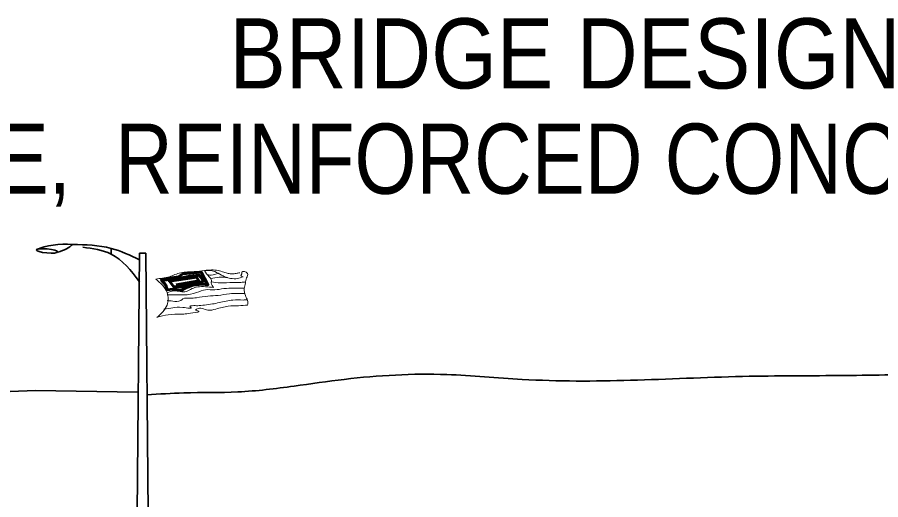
# Model space of a CAD drawing. Extents: x 763.8 to 797.8, y -170.3 to -127.3.
# Drawn here: x 775.84 to 783.6, y -141.62 to -137.29 of the extents above; entities that cross this region are included whole.
import ezdxf
from ezdxf.enums import TextEntityAlignment as Align

# ---------------------------------------------------------------- set-up
doc = ezdxf.new("R2010")
doc.units = 0
doc.header["$LTSCALE"] = 0.077
doc.layers.add('1', color=7, linetype='Continuous', lineweight=35)
doc.layers.add('63', color=7, linetype='Continuous', lineweight=13)

msp = doc.modelspace()

# ---------------------------------------------------------------- linework, layer by layer
at = {"layer": '63', "lineweight": 35}
for p, q in [((776.68675, -139.41675), (776.68675, -139.36583)), ((776.9215, -141.7415), (776.94183, -139.40917)), ((776.94183, -139.40917), (776.99792, -139.40917)), ((777.01825, -141.7415), (776.99792, -139.40917))]:
    msp.add_line(p, q, dxfattribs=at)
at = {"layer": '63', "lineweight": 60}
msp.add_lwpolyline([(777.13792, -139.64592), (777.29075, -139.6205), (777.33142, -139.595), (777.49442, -139.57975), (777.5555, -139.69175), (777.50458, -139.68667), (777.42317, -139.69683), (777.35183, -139.72233), (777.31108, -139.74267), (777.23975, -139.7325), (777.18883, -139.73758), (777.17867, -139.69683), (777.13792, -139.651), (777.23975, -139.64592), (777.39258, -139.61542), (777.474, -139.60517), (777.525, -139.66125), (777.37217, -139.69175), (777.31108, -139.71217), (777.25, -139.71217), (777.20925, -139.66125), (777.45367, -139.62558), (777.474, -139.65608), (777.27033, -139.69175)], dxfattribs=at)
at = {"layer": '63', "lineweight": 35}
msp.add_lwpolyline([(773.95008, -140.723), (776.00742, -140.6415), (776.92408, -140.65583)], dxfattribs=at)
msp.add_ellipse((776.11128, -139.38876), major_axis=(-0.09702, 0.00914), ratio=0.186282, dxfattribs=at)
for centre, major_axis, start_param, end_param in [((776.27808, -139.52381), (-0.39222, 0), 4.5527163, 5.4492329), ((776.07733, -139.26976), (0.28954, 0), 5.1807329, 5.8525401)]:
    msp.add_ellipse(centre, major_axis=major_axis, ratio=0.5, start_param=start_param, end_param=end_param, dxfattribs=at)
for points in [[(776.94133, -139.46767), (776.68675, -139.36583), (776.34042, -139.33017)], [(776.94133, -139.66558), (776.68675, -139.41675), (776.43208, -139.35567)], [(777.009, -140.68083), (777.33933, -140.66317), (777.82533, -140.65442), (778.32867, -140.60242), (778.77992, -140.54167), (779.69992, -140.49825), (780.37683, -140.54167), (781.34883, -140.55033), (782.3555, -140.51558), (783.2755, -140.50692), (784.09125, -140.49825), (784.76817, -140.48958), (786.01792, -140.33333), (787.70158, -140.36808)]]:
    msp.add_spline(points, degree=3, dxfattribs=at)
at = {"layer": '63'}
for points in [[(777.087, -139.64083), (777.20925, -139.6205), (777.31108, -139.58483), (777.43325, -139.57467), (777.525, -139.56442), (777.61667, -139.57467), (777.67775, -139.60517), (777.70825, -139.6205), (777.75925, -139.63575), (777.82033, -139.63575), (777.87125, -139.6205)], [(777.525, -139.56442), (777.64717, -139.56442), (777.69808, -139.57975), (777.73883, -139.58992), (777.76942, -139.595), (777.81017, -139.58992), (777.84067, -139.58483)], [(777.525, -139.56442), (777.56575, -139.6205), (777.58608, -139.64592), (777.58608, -139.6765), (777.60642, -139.71725)], [(777.5535, -139.60367), (777.58608, -139.60517), (777.64717, -139.58992)], [(777.87125, -139.6205), (777.85083, -139.61025), (777.86108, -139.595), (777.86108, -139.57975), (777.912, -139.58992), (777.90183, -139.63067), (777.89158, -139.6765), (777.88142, -139.72742), (777.89158, -139.7885), (777.912, -139.83433), (777.912, -139.87508)], [(777.087, -139.64083), (777.18883, -139.76308), (777.18883, -139.87508), (777.09725, -139.98717)], [(777.579, -139.63717), (777.65733, -139.62558), (777.73225, -139.62767)], [(777.58608, -139.66633), (777.6675, -139.6765), (777.77958, -139.67142), (777.85083, -139.67142), (777.89383, -139.66642)], [(777.18883, -139.76308), (777.25, -139.74775), (777.362, -139.75292), (777.41292, -139.72742), (777.46383, -139.71217), (777.60642, -139.71725)], [(777.18883, -139.78342), (777.29075, -139.78342), (777.34167, -139.78342), (777.45367, -139.76308), (777.53517, -139.73758), (777.61667, -139.73758), (777.69808, -139.72742), (777.78975, -139.72233), (777.88225, -139.72342)], [(777.15883, -139.91175), (777.23975, -139.90058), (777.33142, -139.89542), (777.40275, -139.89542), (777.39258, -139.88525), (777.41292, -139.88017), (777.46383, -139.88017), (777.525, -139.87508), (777.59625, -139.86492), (777.7185, -139.83942), (777.77958, -139.82925), (777.87125, -139.82925), (777.90892, -139.82733)], [(777.18883, -139.83433), (777.23975, -139.83942), (777.31108, -139.83433), (777.33142, -139.81908), (777.39258, -139.814), (777.45367, -139.80892), (777.5555, -139.79358), (777.64717, -139.7885), (777.749, -139.77325), (777.88875, -139.77125)], [(777.10075, -139.98275), (777.19908, -139.96167), (777.31108, -139.95658), (777.4435, -139.94133), (777.474, -139.93108), (777.46383, -139.926), (777.4435, -139.92092), (777.45367, -139.91075), (777.50458, -139.90567), (777.5555, -139.92092), (777.62683, -139.91075), (777.73883, -139.88525), (777.8305, -139.88017), (777.912, -139.87508)]]:
    msp.add_spline(points, degree=3, dxfattribs=at)

# ---------------------------------------------------------------- texts
at = {"layer": '1'}
for s, width, p in [('BRIDGE DESIGN', 0.9, (780.76075, -137.93058)), ('PRESTRESSED CONCRETE,  REINFORCED CONCRETE AND STEEL STRUCTURES', 0.85, (780.76067, -138.87558))]:
    msp.add_text(s, height=0.63, dxfattribs=dict(at, width=width)).set_placement(p, align=Align.CENTER)

doc.saveas('drawing.dxf')
